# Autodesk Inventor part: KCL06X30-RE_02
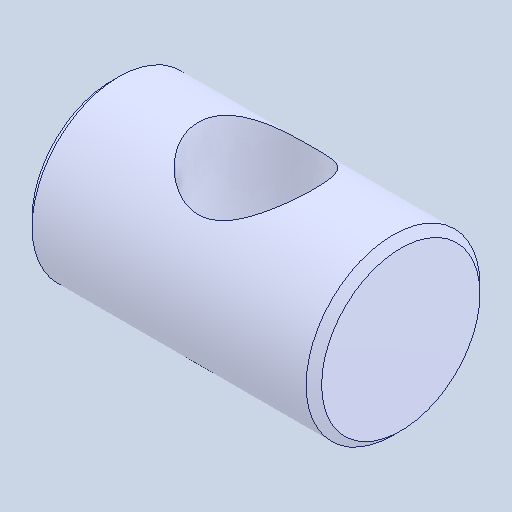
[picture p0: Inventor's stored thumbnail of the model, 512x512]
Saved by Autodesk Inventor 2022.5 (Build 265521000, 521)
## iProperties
Created: 2024-08
Part Number: KCL06X30-RE_02
Material: 一般
Document SubType Name: Modeling
Designer: ImaoCorp
Density: 1 g/cm^3
Appearance: 既定
Author: ImaoCorp
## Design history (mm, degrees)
feature "KCL06X30-RE_02"
node "ソリッド1"
